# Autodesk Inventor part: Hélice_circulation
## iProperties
Shininess: 64.0
Length Units: 11269
Angle Units: 11279
Time Units: 11290
Mass Units: 11283
Length Display Precision: 3
Angle Display Precision: 2
Compacted: True
Part Number: Hélice_circulation
Document SubType Name: Modeling
Created: 2008-02
Material: Acier inoxydable, austénitique
Designer: Pascal
Density: 0.0
Volumn: 0.0
Area: 0.0
PropertySet Name: Model Information
Control State: 0
Master: False
Checked Out: False
DESIGNATION: Hélice de circulation
Author: Pascal
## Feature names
1. Hélicoïde1
